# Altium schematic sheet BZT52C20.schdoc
size 127 x 101 mm
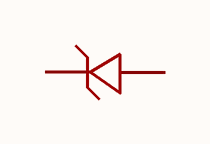
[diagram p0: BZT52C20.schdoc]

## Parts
D?  bzt52c20_c173424  [SOD-123_L2.7-W1.6-LS3.7-RD]  (value not drawn)

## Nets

Not connected (* = marked no-connect by the designer): D? 1(K) 2(A)

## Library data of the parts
D? = bzt52c20_c173424: 二极管配置:1个独立式;稳压值(标称值):20V;稳压值(范围):19V~21V;耗散功率(Pd):500mW;; Manufacturer: MDD(辰达半导体); AddInBom: yes; ModelId: ad7e39f9e5534b3c96ffdc5532ebb493; ModelName: SOD-123_L2.7-W1.6-H1.4-LS3.7; ModelTransform: 146.026,62.992,0,180,0,0,0.0005,0,0; Diode Configuration: 1个独立式; Zener Voltage(Nom): 20V; Reverse Leakage Current (Ir): 100nA@15V; Pd - Power Dissipation: 500mW; Impedance(Zzt): 50Ω; Tolerance: ±5%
